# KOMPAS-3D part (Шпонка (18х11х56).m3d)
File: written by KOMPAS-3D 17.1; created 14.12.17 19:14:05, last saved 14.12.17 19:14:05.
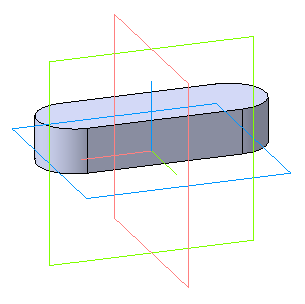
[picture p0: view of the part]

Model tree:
1. Операция без истории:1  (labels: Шпонка (18х11х56))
